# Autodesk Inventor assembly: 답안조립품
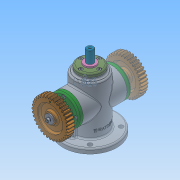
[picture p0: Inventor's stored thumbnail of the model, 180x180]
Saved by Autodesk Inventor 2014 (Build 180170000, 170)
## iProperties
Created: 2020-06
Part Number: 답안조립품
Document SubType Name: Assembly
Designer: NET
Mass: 1352.06 g
Surface Area: 1735.34 cm^2
Volume: 519.372 cm^3
Density: 2.60326 g/cm^3
Author: NET
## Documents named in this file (17)
- C:\Users\NET\Desktop\600606V1017\답안조립품.iam
- C:\Users\NET\Desktop\600606V1017\본체.ipt
- C:\Users\NET\Desktop\600606V1017\가변스프링.ipt
- C:\Users\NET\Desktop\600606V1017\멈춤링.ipt
- C:\Users\NET\Desktop\600606V1017\베어링 6203.ipt
- C:\Users\NET\Desktop\600606V1017\볼트 M4.ipt
- C:\Users\NET\Desktop\600606V1017\부시.ipt
- C:\Users\NET\Desktop\600606V1017\스퍼기어.ipt
- C:\Users\NET\Desktop\600606V1017\스프링와셔.ipt
- C:\Users\NET\Desktop\600606V1017\스프링조립용 와셔.ipt
- C:\Users\NET\Desktop\600606V1017\슬라이더.ipt
- C:\Users\NET\Desktop\600606V1017\오일 실 17 30 8.ipt
- C:\Users\NET\Desktop\600606V1017\커버 A.ipt
- C:\Users\NET\Desktop\600606V1017\커버 B.ipt
- C:\Users\NET\Desktop\600606V1017\키 4x4x12.ipt
- C:\Users\NET\Desktop\600606V1017\편심축.ipt
- C:\Users\NET\Desktop\600606V1017\평와셔.ipt
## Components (1 placed, 1 different names)
1. 가변스프링:1
## Named parameters: d11_d10 = 0, d25_d23 = 0, d26_d24 = 0
